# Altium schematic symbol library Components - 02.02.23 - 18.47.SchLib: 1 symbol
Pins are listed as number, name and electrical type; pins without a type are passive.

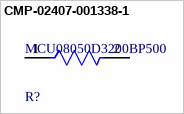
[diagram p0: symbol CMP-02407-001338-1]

## CMP-02407-001338-1
designator R?, comment MCU08050D3200BP500
RES 1.05K OHM 0.5% 1/5W 0805; Resistance: 320R; Tolerance: 0.1%; Temperature Coefficient: 25ppm/°C
footprint FP-MCU0805-IPC_C
footprint FP-MCU0805-IPC_A
footprint FP-MCU0805-IPC_B
footprint FP-MCU0805-MFG
pins: 1, 2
